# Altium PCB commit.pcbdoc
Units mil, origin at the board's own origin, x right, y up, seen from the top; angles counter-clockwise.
Board outline 1653.54 x 3149.61 mil, 2 copper layers (Top Layer, Bottom Layer); 82 components, 52 nets, 246 pads, 237 vias.
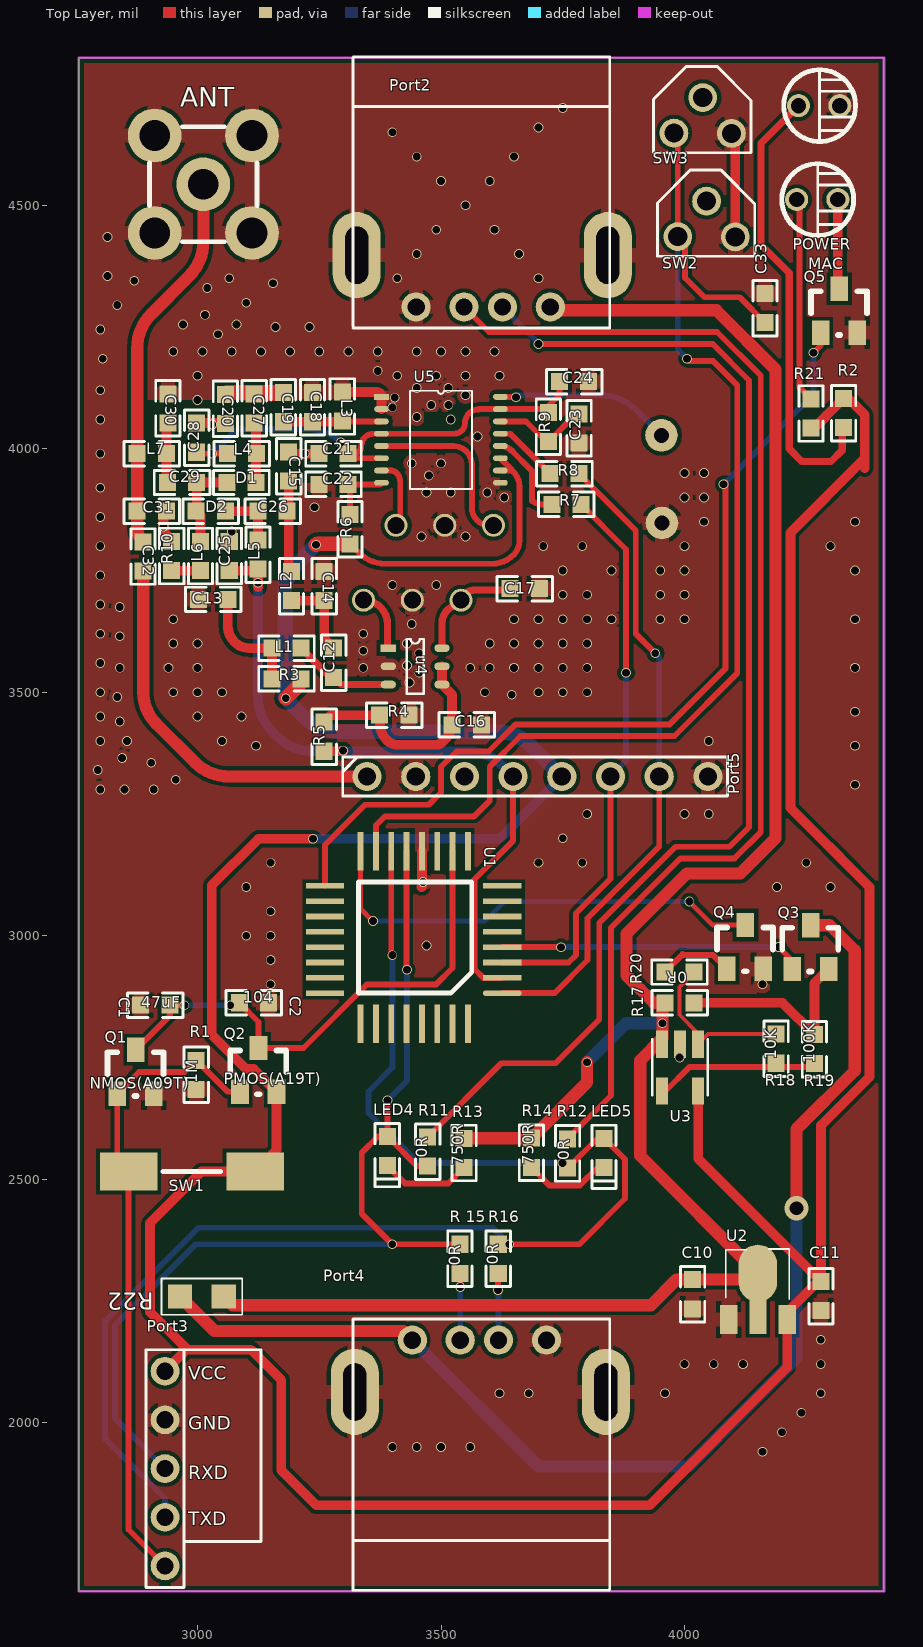
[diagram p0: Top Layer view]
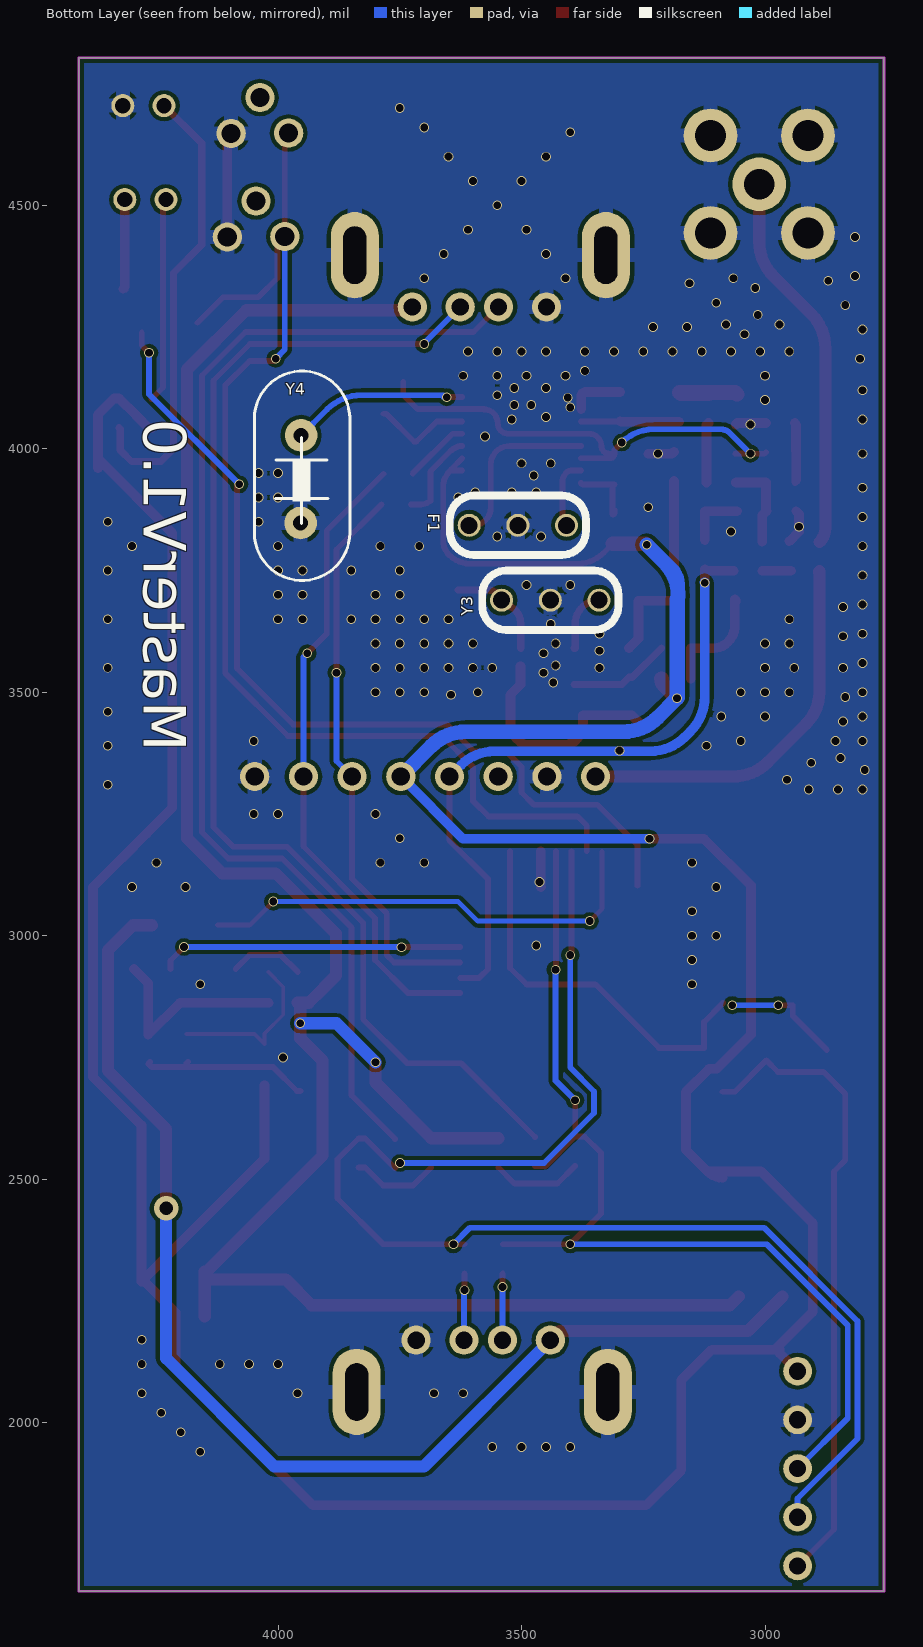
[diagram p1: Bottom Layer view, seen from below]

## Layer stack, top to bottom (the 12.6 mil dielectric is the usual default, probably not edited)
Top Layer: signal copper 1.4
Dielectric: dielectric 12.6, FR-4, Dk 4.8
Bottom Layer: signal copper 1.4

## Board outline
2755.91,1653.54 4409.45,1653.54 4409.45,4803.15 2755.91,4803.15

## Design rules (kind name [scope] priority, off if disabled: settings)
Clearance [All] p1: gap=8
ComponentClearance [All] p1: gap=0 collisioncheckmode=3 verticalgap=0 showdistances=FALSE
MinimumSolderMaskSliver [All] p1: minsoldermaskwidth=0
PolygonConnect [All] p1: connectstyle=Relief reliefconductorwidth=30 reliefentries=4 polygonreliefangle="90 Angle"
RoutingVias [All] p1: holewidth=50 width=100 viastyle="Through Hole" minholewidth=1 minwidth=10 maxholewidth=28 maxwidth=50
SilkToSilkClearance [All] p1: silktosilkclearance=0
SilkscreenOverComponentPads [All] p1: minsilkscreentomaskgap=0
SolderMaskExpansion [All] p1: expansion=4
Width [All] p1: maxlimit=30 minlimit=7 preferedwidth=15
24 further rules are at their usual default settings.

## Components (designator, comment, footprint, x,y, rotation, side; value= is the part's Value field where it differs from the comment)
ANT "SMA" SWA-KE天线母座 3011.81,4543.31 r0 top
C1 "47uF" 0603 2883,2857.17 r0 top
C2 "104" 0603 3145.67,2862.2 r180 top
C10 "10uF" 0603 4016.61,2293.64 r270 top
C11 "104" 0603 4280.39,2289.7 r270 top
C12 "220pF5%" 0603 3279.53,3590.55 r270 top
C13 "104" 0603 3001.97,3690.63 r0 top
C14 "4.7pF5%" 0603 3259.84,3748.03 r270 top
C15 "12pF5%" 0603 3187.01,3993.78 r270 top
C16 "104" 0603 3582.68,3433.07 r180 top
C17 "1pF" 0603 3641.73,3712.6 r0 top
C18 "NC" 0603 3235.98,4115.51 r270 top
C19 "1pF5%" 0603 3175.98,4115.51 r270 top
C20 "NC" 0603 3057.08,4111.89 r270 top
C21 "104" 0603 3309.05,3989.84 r180 top
C22 "104" 0603 3309.05,3926.85 r180 top
C23 "104" 0603 3783.46,4011.81 r90 top
C24 "104" 0603 3803.15,4137.8 r180 top
C25 "NC" 0603 3064.96,3749.69 r90 top
C26 "NC" 0603 3124.01,3871.73 r0 top
C27 "NC" 0603 3116.14,4052.84 r90 top
C28 "1045%" 0603 2998.03,4052.84 r270 top
C29 "220pF5%" 0603 2998.03,3930.79 r180 top
C30 "NC" 0603 2938.97,4052.84 r90 top
C31 "NC" 0603 2875.98,3871.73 r0 top
C32 "NC" 0603 2887.79,3808.74 r270 top
C33 "NC" 0603 4165.35,4318.9 r270 top
D1 "SMP1320" 0603 3120.08,3930.79 r180 top
D2 "SMP1320" 0603 3057.08,3871.73 r180 top
F1 "10.7M" "PT4450 XTAL" 3507.6,3842.8 r0 bottom
L1 "180nH5%" 0603 3212.6,3590.55 r180 top
L2 "22nH5%" 0603 3192.91,3748.03 r270 top
L3 "47nH5%" 0603 3297.24,4056.77 r90 top
L4 "180nH5%" 0603 3061.02,3989.84 r0 top
L5 "180nH5%" 0603 3124.01,3812.68 r270 top
L6 "180nH5%" 0603 3005.9,3749.69 r90 top
L7 "0R" 0603 2875.98,3989.84 r0 top
LED4 "RX" LED-0603 3389.76,2527.56 r90 top
LED5 "TX" LED-0603 3834.65,2523.62 r90 top
MAC "MAC" 2.54LED 4322.83,4511.81 r0 top
Port2 "USB_A" USB-A 3586.61,4291.34 r180 top
Port3 "DEBUG" STC_DEBUG 2933.07,1905.51 r0 top
Port4 "USB_B" USB-A 3578.74,2169.29 r0 top
Port5 "Mold" Pin-8 3748.03,3326.77 r90 top
POWER "POWER" 2.54LED 4326.77,4704.72 r0 top
Q1 "NMOS(A09T)" SOT-23 2870.08,2720.47 r0 top
Q2 "PMOS(A19T)" SOT-23 3122.05,2724.41 r0 top
Q3 "AO3407(P)" SOT-23 4255.91,2976.38 r0 top
Q4 "9014" SOT-23 4122.05,2976.76 r0 top
Q5 "NMOS(A09T)" SOT-23 4314.96,4283.46 r0 top
R1 "1M" 0603 2997.17,2683.94 r90 top
R2 "2.2K" 0603 4326.77,4043.31 r90 top
R3 "0R" 0603 3212.6,3527.56 r180 top
R4 "100k" 0603 3374.02,3452.76 r0 top
R5 "0R" 0603 3259.84,3378.77 r90 top
R6 "10R" 0603 3312.99,3804.8 r90 top
R7 "10K" 0603 3787.4,3885.83 r180 top
R8 "10K" 0603 3783.46,3948.82 r180 top
R9 "5.1M" 0603 3720.47,4074.8 r270 top
R10 "3.3K" 0603 2946.85,3749.69 r90 top
R11 "0R" 0603 3472.44,2586.61 r270 top
R12 "0R" 0603 3759.84,2582.68 r270 top
R13 "750R" 0603 3547.24,2523.62 r90 top
R14 "750R" 0603 3685.6,2524.06 r90 top
R16 "0R" 0603 3617.46,2306.19 r90 top
R17 "RES" 0603 4019.94,2862.13 r180 top
R18 "10K" 0603 4188.14,2737.91 r90 top
R19 "100K" 0603 4266.88,2796.97 r270 top
R20 "0R" 0603 4019.68,2925.2 r180 top
R21 "0R" 0603 4259.84,4102.36 r270 top
R22 "0R" 0805 3003.94,2263.78 r180 top
"R 15" "0R" 0603 3538.72,2306.19 r90 top
SW1 "REST" SW-1 3047.24,2437.01 r270 top
SW2 "REST" Key1 4102.36,4433.07 r180 top
SW3 "REST" Key1 4094.49,4645.67 r180 top
U1 "STC8F2K32S2" LQPF-32 3590.55,2846.46 r180 top
U2 "HT7533-1" 3A5A3D 4150.78,2211.88 r0 top
U3 "LM321" AD8628 3988.19,2732.28 r180 top
u4 "PT4450" PT4450 3389.76,3586.61 r270 top
U5 "PT4302" PT4302 3377.68,4106.58 r0 top
Y3 "433.92M" "PT4450 XTAL" 3440.94,3688.98 r180 bottom
Y4 "13.226M" "PT4306 XTAL" 3952.76,4027.56 r270 bottom

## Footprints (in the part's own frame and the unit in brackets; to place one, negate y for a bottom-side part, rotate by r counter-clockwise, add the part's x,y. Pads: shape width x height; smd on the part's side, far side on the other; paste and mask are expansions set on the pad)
2.54LED [mm]
  round 1.2 hole 0.8: 1(-2.35,0) 2(-0.2,0)
  silkscreen extent -3.12,-1.87 0.62,1.9
3A5A3D [mm]
  rect 0.9x1.5 smd: 1(-1.524,0) 3(1.524,0)
  rect 0.9x1.8 smd: 2(0,0.15)
  oval 2x3 smd: 2(0,2.4)
  silkscreen extent -1.68,1.07 1.63,3.67
0603 [mil]
  rect 35x35 smd: 1(0,0) 2(60,0)
  silkscreen extent -27,-25 87,25
0805 [mil]
  rect 50x50 smd: 1(-50,5) 2(40,5)
  silkscreen extent -88,-32 78,42
AD8628 [mil]
  rect 24x56 smd: 1(-39.61,-44.88) 2(-2.61,-44.88) 3(34.39,-44.88) 4(34.39,51.12) 5(-39.61,51.12)
  silkscreen extent -60,-55 54,60
Key1 [mm]
  round 1.5 / inner round 1.524 / far side round 1.524 hole 1: 1(2.95,-0.067) 2(-0.05,-0.05) ""(1.45,-1.92)
  silkscreen extent -1.07,-3.55 4.01,0.95
LED-0603 [mil]
  rect 35x35 smd: 1(0,0) 2(60,0)
  silkscreen extent -43,-25 87,25
LQPF-32 [mm]
  oct 2x0.3 smd: 1(-0.9,-0.9)
  rect 2x0.3 smd: 2(-0.9,-1.7) 3(-0.9,-2.5) 4(-0.9,-3.3) 5(-0.9,-4.1) 6(-0.9,-4.9) 7(-0.9,-5.7) 8(-0.9,-6.5) 17(8.35,-6.5) 18(8.35,-5.7) 19(8.35,-4.9) 20(8.35,-4.1) 21(8.35,-3.3) 22(8.35,-2.5) 23(8.35,-1.7) 24(8.35,-0.9)
  rect 0.3x2 smd: 9(0.9,-8.3) 10(1.7,-8.3) 11(2.5,-8.3) 12(3.3,-8.3) 13(4.1,-8.3) 14(4.9,-8.3) 15(5.7,-8.3) 16(6.5,-8.3) 25(6.5,0.7) 26(5.7,0.7) 27(4.9,0.7) 28(4.1,0.7) 29(3.3,0.7) 30(2.5,0.7) 31(1.7,0.7) 32(0.9,0.7)
  silkscreen extent 0.7,-6.7 6.6,-0.9
Pin-8 [mil]
  round 60 hole 37.4: 1(0,400) 2(0,300) 3(0,200) 4(0,100) 5(0,0) 6(0,-100) 7(0,-200) 8(0,-300)
  silkscreen extent -40,-340 40,450
PT4302 [mil]
  rect 30x12 smd: 1(0,0)
  oval 30x12 smd: 2(0,-25.2) 3(0,-50.39) 4(0,-75.59) 5(0,-100.79) 6(0,-125.98) 7(0,-151.18) 8(0,-176.38) 9(244.09,-176.38) 10(244.09,-151.18) 11(244.09,-125.98) 12(244.09,-100.79) 13(244.09,-75.59) 14(244.09,-50.39) 15(244.09,-25.2) 16(244.09,0)
  silkscreen extent 58,-189 186,13
"PT4306 XTAL" [mil]
  round 66.93 hole 31: 1(0,0) 2(180,-1)
  silkscreen extent -132,-96 298,100
PT4450 [mm]
  rect 0.4x0.8 smd: 1(-0.1,0.05)
  oval 0.4x0.8 smd: 2(0.85,0.05) 3(1.8,0.05) 4(1.8,2.85) 5(0.85,2.85) 6(-0.1,2.85)
  silkscreen extent -0.57,1 2.28,1.89
"PT4450 XTAL" [mm]
  round 1.2 hole 0.889: 1(-2.54,0) 2(0,0) 3(2.54,0)
  silkscreen extent -3.56,-1.55 3.56,1.55
SOT-23 [mil]
  rect 36x50 smd: 1(40,-45) 2(-35,-45) 3(3,45)
  silkscreen extent -55,-50 60,40
STC_DEBUG [mm]
  round 1.5 hole 0.9: 1(0,5.08) 2(0,2.54) 3(0,0) 4(0,-2.54) 5(0,-5.08)
  silkscreen extent -1,-6.2 5,6.2
SW-1 [mm]
  rect 2x3 smd: 1(-2,1.8) 2(-2,-4.8)
  silkscreen extent -2,-3 -2,0
SWA-KE天线母座 [mm]
  round 2.8 hole 1.6: 1(0,0) 2(-2.54,-2.54) 2(-2.54,2.54) 2(2.54,-2.54) 2(2.54,2.54)
  silkscreen extent -2.8,-3 2.8,3
USB-A [mm]
  round 1.524 hole 0.9: 1(-3.5,0) 2(-1,0) 3(1,0) 4(3.5,0)
  oval 2.5x4.5 hole 1.2 slot 3 at 90 deg: 4(-6.5,-2.7) 4(6.6,-2.7)
  silkscreen extent -6.6,-13.05 6.8,1.1

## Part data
ANT L1 L2 L3 R1 R2 R3 R4 R5 R6 R7 R8 R9 R10 R11 R12 R13 R14 R16 R17 R18 R19 R20 R21 R22 "R 15": library part Res2, "Resistor"
C1 C2 C10 C11 C12 C13 C14 C15 C16 C17 C18 C19 C20 C21 C22 C23 C24 C25 C26 C27 C28 C29 C30 C31 C32 C33: library part Cap, "Capacitor"
D1 D2 LED4 LED5 MAC POWER: library part DIODE, "diode"
F1: library part Filter
L4 L5 L6 L7: library part L, "Inductor"
Port2 Port4: library part USB
Port3: library part PIN-5
Port5: library part Pin-8
Q1 Q5: library part MOSFET-N, "mosfet"
Q2 Q3: library part MOSFET-P, "mosfet"
Q4: library part 2N3904, "NPN General Purpose Amplifier"
SW1 SW2 SW3: library part SW-P, "key"
U1: library part STC8F2K64S2
U3: library part AD8628
Y3: library part PT4450-XTAL
Y4: library part XTAL, "Crystal Oscillator"

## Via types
v1: diameter 20, hole 16, Top Layer to Bottom Layer, 236 vias
v2: diameter 50, hole 28, Top Layer to Bottom Layer, 1 vias

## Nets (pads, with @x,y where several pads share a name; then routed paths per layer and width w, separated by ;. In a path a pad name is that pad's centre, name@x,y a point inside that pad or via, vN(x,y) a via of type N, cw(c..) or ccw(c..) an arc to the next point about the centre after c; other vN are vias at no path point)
ANT: ANT.1 C31.1 C32.1 L7.1 | length 785.4
  Top Layer w25: C32.1 cw(c2916.31,3837.26) 2875.98,3837.26 C31.1 L7.1 2875.98,4206.32 cw(c2975.98,4206.32) 2905.27,4277.03 2982.52,4354.28 ccw(c2911.81,4424.99) 3011.81,4424.99 ANT.1
CEOUT: Q3.2 U1.4 | length 669.8
  Top Layer w12: U1.4 v1(3746.38,2976.38) ; v1(4193.24,2976.76) 4220.91,2949.09 Q3.2
  Bottom Layer w12: v1(3746.38,2976.38) 3824.62,2976.38 ; 4160,2976.76 4140,2976.76 ; v1(4193.24,2976.76) 4140,2976.76 ; 3824.62,2976.38 3825,2976.76 3850,2976.76 ; 3824.62,2976.38 3849.62,2976.38 3850,2976.76 ; 3850,2976.76 4140,2976.76
CNET: Q4.3 U1.16 | length 955.3
  Top Layer w10: U1.16 3334.65,3055.35 v1(3360,3030) ; v1(4010,3070) 4058.24,3021.76 Q4.3
  Bottom Layer w10: v1(3360,3030) 3590,3030 3630,3070 v1(4010,3070)
GND: ANT.2 C1.1 C2.1 C10.2 C11.2 C13.1 C14.1 C15.1 C16.1 C17.2 C18.1 C20.2 C21.2 C22.2 C23.1 C24.1 C25.2 C28.1 C30.2 C31.2 C33.1 F1.2 L3.2 Port2.4 Port3.2 Port4.4 Port5.2 Port5.8 POWER.2 Q1.1 Q4.1 Q5.1 R1.1 R4.2 R10.2 SW2.2 SW3.2 U1.12 U2.1 U3.2 u4.2 U5.1 U5.2 U5.9 Y3.2 Y4.2 | length 591.1
  Top Layer w20: C31.2 2930,3865.75 v1(2930,3840) 2930,3830 R10.2@2950,3810 ; C28.1 3057.16,4052.84 C20.2@3060,4050 ; C15.1 3190.79,3990 C21.2@3240,3990 ; L3.2 3367.48,4116.77 cw(c3367.48,4106.58) U5.1 U5.2 ; 3460,3100 ccw(c3460,3100.63) 3460.63,3100.63 U1.12 ; SW3.2 4104.33,4639.76 SW2.2
  other v1: 4160,1940 3400,1950 3450,1950 3500,1950 3560,1950 4200,1980 4240,2020 3620,2060 3680,2060 3960,2060 4280,2060 4000,2120 4060,2120 4120,2120 4280,2120 4280,2170 3990,2750 3150,2900 4160,2900 3150,2950 3470,2980 3100,3000 3150,3000 3150,3050 3100,3100 4190,3100 4300,3100 3463,3110.24 3150,3150 3700,3150 3790,3150 4250,3150 3750,3200 3800,3250 4000,3250 4050,3250 2800,3300 2850,3300 2910,3300 4350,3310 2955,3320 2795,3340 2905,3355 2845,3365 3120,3390 4350,3390 2800,3400 2855,3400 3050,3400 4050,3400 2840,3440 2800,3450 3000,3450 3090,3450 4350,3460 2835,3490 3645,3495 2800,3500 2950,3500 3000,3500 3050,3500 3590,3500 3700,3500 3750,3500 3800,3500 3435,3520 3455,3540 2840,3550 2940,3550 3000,3550 3340,3550 3560,3550 3600,3550 3650,3550 3700,3550 3750,3550 3800,3550 4350,3550 3430,3555 2800,3560 3455,3580 3340,3585 2950,3600 3000,3600 3430,3600 3600,3600 3650,3600 3700,3600 3750,3600 3800,3600 2840,3615 2800,3620 3340,3620 3440,3640 2950,3650 3650,3650 3700,3650 3750,3650 3800,3650 3850,3650 3950,3650 4000,3650 4350,3650 2840,3675 2800,3680 3750,3700 3800,3700 3950,3700 4000,3700 3400,3720 3490,3720 2800,3740 3750,3750 3850,3750 3950,3750 4000,3750 4350,3750 2800,3800 3710,3800 3790,3800 4000,3800 4300,3800 3460,3820 3550,3820 3070,3830 4040,3850 4350,3850 2800,3860 3240,3880 3630,3900 4000,3900 4040,3900 3470,3910 3520,3910 3595,3910 2800,3920 3475,3945 4000,3950 4040,3950 3440,3970 3500,3970 2800,3990 3220,3990 3575,4025 3030,4050 2800,4060 3520,4060 3450,4065 3400,4085 3480,4090 3515,4090 3000,4100 3405,4105 3550,4110 2800,4120 3450,4125 3515,4125 3000,4150 3410,4150 3490,4150 3550,4150 3620,4150 3370,4160 2805,4185 2950,4200 3010,4200 3070,4200 3130,4200 3190,4200 3250,4200 3310,4200 3370,4200 3450,4200 3500,4200 3550,4200 3610,4200 3042,4235 2800,4245 3160,4250 3230,4250 2970,4255 3080,4255 3015,4275 2835,4295 3100,4300 3020,4330 3155,4340 2870,4345 3065,4350 3410,4350 3700,4350 2815,4355 3450,4400 3660,4400 2815,4435 3490,4450 3610,4450 3550,4500 3500,4550 3600,4550 3450,4600 3650,4600 3400,4650 3700,4660 3750,4700
NetC12_1: C12.1 C14.2 L2.2 | length 172.6
  Top Layer w20: L2.2 C14.2 3259.84,3610.24 C12.1
NetC12_2: C12.2 L1.1 u4.3 | length 210.1
  Top Layer w15: L1.1 3272.6,3530.55 C12.2 3294.33,3515.75 u4.3
NetC13_2: C13.2 L1.2 R3.2 | length 239.8
  Top Layer w20: C13.2@3059.91,3685.67 cw(c3066.92,3685.67) C13.2 3061.97,3637.21 ccw(c3110.77,3637.21) 3076.26,3602.7 ccw(c3105.6,3632.05) 3105.6,3590.55 L1.2 R3.2
NetC16_2: C16.2 R4.1 R5.2 u4.4 u4.5 | length 464
  Top Layer w20: R5.2 3273.83,3452.76 R4.1 3374.02,3437.65 ccw(c3425.83,3437.65) 3389.19,3401.01 ccw(c3411.24,3423.06) 3411.24,3391.88 3489.67,3391.88 ccw(c3489.67,3408.57) 3501.46,3396.77 3512.01,3407.31 ccw(c3486.25,3433.07) C16.2 3522.68,3495.04 u4.4 u4.5
NetC17_1: C17.1 u4.6 Y3.1 | length 227
  Top Layer w15: u4.6 3501.97,3641.97 cw(c3540,3641.97) 3540,3680 cw(c3570,3680) 3570,3710 C17.1@3630,3710
  Top Layer w30: Y3.1 Y3.1@3547.09,3695.12
NetC18_2: C18.2 C19.2 L3.1 U5.3 | length 203.9
  Top Layer w12: L3.1@3295.98,4055.51 cw(c3296.65,4055.51) 3296.65,4056.18 U5.3
  Top Layer w20: C19.2 C18.2 3295.98,4055.51 L3.1
NetC22_1: C22.1 R6.2 U5.8 | length 219.5
  Top Layer w12: U5.8 cw(c3374.33,3930.2) 3374.33,3926.85 C22.1 ; R6.2@3309.05,3868.74 ccw(c3312.99,3868.74) R6.2 ; R6.2@3309.05,3868.74 ccw(c3312.99,3868.74) R6.2 ; R6.2@3309.05,3868.74 ccw(c3312.99,3868.74) R6.2 ; R6.2@3309.05,3868.74 ccw(c3312.99,3868.74) R6.2 ; C22.1 cw(c3309.05,3922.92) C22.1@3312.99,3922.92 ; C22.1 cw(c3309.05,3922.92) C22.1@3312.99,3922.92 ; C22.1 cw(c3309.05,3922.92) C22.1@3312.99,3922.92 ; C22.1 cw(c3309.05,3922.92) C22.1@3312.99,3922.92 ; C22.1 cw(c3309.05,3922.92) C22.1@3312.99,3922.92 ; C22.1 cw(c3309.05,3922.92) C22.1@3312.99,3922.92 ; C22.1 3312.99,3926.85 R6.2 ; R6.2 cw(c3322.49,3874.31) 3309.05,3874.31 ccw(c3322.49,3874.31) R6.2
NetC23_2: C23.2 R9.2 U5.14 | length 202.4
  Top Layer w12: U5.14 3674.27,4056.18 3715.64,4014.8 3720.93,4014.8 3777.94,4071.81 C23.2
NetC26_1: C26.1 D2.1 L5.1 | length 126
  Top Layer w20: D2.1 C26.1 L5.1
NetC27_1: C27.1 D1.1 L4.2 | length 123.7
  Top Layer w20: C27.1 3120.08,4048.9 D1.1
NetC29_1: C29.1 D1.2 D2.2 L6.2 | length 197.3
  Top Layer w15: C29.1@2997.08,3928.51 cw(c3000.31,3928.51) C29.1 ccw(c3000.31,3928.51) C29.1@2997.08,3928.51
  Top Layer w20: L6.2 3005.9,3862.92 D2.2 ; D1.2 C29.1 2998.03,3872.68 D2.2 ; D2.2 ccw(c2994.8,3874.02) 2998.03,3874.02 cw(c2994.8,3874.02) D2.2
NetC29_2: C29.2 C30.1 L7.2 | length 195.2
  Top Layer w15: C29.2@2935.98,3935.73 ccw(c2942.97,3935.73) C29.2 ; L7.2 ccw(c2928.76,3997.07) 2938.97,3997.07 C30.1
  Top Layer w20: C29.2@2935.98,3935.73 L7.2 C30.1@2935.98,4045.61 ; C30.1@2935.98,4045.61 cw(c2946.2,4045.61) C30.1 ccw(c2946.2,4045.61) C30.1@2935.98,4045.61
NetC32_2: C32.2 Port5.1 | length 798.2
  Top Layer w25: C32.2@2889.26,3745.19 ccw(c2884.24,3745.19) C32.2 cw(c2886.33,3747.28) 2888.4,3747.28 2888.4,3500.03 ccw(c2979.98,3500.03) 2915.22,3435.27 2994.43,3356.06 ccw(c3065.15,3426.77) 3065.15,3326.77 Port5.1
NetC33_2: C33.2 SW2.1 SW3.1 U1.15 | length 2448.6
  Top Layer w12: U1.15 3366.14,3226.14 3385,3245 3568,3245 3600.03,3277.03 3600.03,3346.65 3663.38,3410 3979.5,3410 4108.5,3539 4108.5,4130.48 4058.98,4180 4010,4180 v1(4005,4185) ; SW3.1@3986.22,4640.44 SW2.1 4001.28,4435.72 4001.28,4350.72 4040.94,4311.06 4113.2,4311.06 C33.2
  Bottom Layer w12: SW2.1 3986.22,4203.78 v1(4005,4185)
NetF1_1: F1.1 U5.7 | length 144.1
  Top Layer w12: U5.7 3396.22,3955.39 cw(c3396.22,3937.94) 3408.56,3950.28 cw(c3390.05,3931.77) 3416.23,3931.77 3416.23,3873.99 3416.23,3863.65 cw(c3386.75,3863.65) F1.1
NetF1_3: F1.3 U5.5 | length 361.1
  Top Layer w12: U5.5 3524.89,4005.79 cw(c3524.89,3967.38) 3563.31,3967.38 ccw(c3563.31,3967.29) 3563.22,3967.29 3563.22,3878.89 ccw(c3599.32,3878.89) 3599.32,3842.8 F1.3
NetL6_1: L6.1 R10.1 | length 59.1
  Top Layer w20: R10.1 L6.1
NetLED4_1: LED4.1 R13.1 | length 186
  Top Layer w12: LED4.1 3426.21,2491.11 3514.74,2491.11 R13.1
NetLED5_1: LED5.1 R14.1 | length 179.4
  Top Layer w12: R14.1 3722.49,2487.18 3784.8,2487.18 3821.24,2523.62 LED5.1
NetMAC_1: MAC.1 R21.1 | length 421.7
  Top Layer w12: MAC.1 4236.5,4505.63 4236.5,4125.7 R21.1
NetMAC_2: MAC.2 Q5.3 | length 197
  Top Layer w20: MAC.2@4306.15,4503 MAC.2 4314.96,4331.46 Q5.3
NetPort2_2: Port2.2 R11.1 | length 2527.7
  Top Layer w12: R11.1 3623.83,2738 3735,2738 3825,2828 3825,3025.94 3981.56,3182.5 4092.43,3182.5 4132.5,3222.57 4132.5,4140.43 4057.93,4215 v1(3700,4215)
  Bottom Layer w12: Port2.2 3700,4217.32 v1(3700,4215)
NetPort2_3: Port2.3 R12.1 | length 2464.6
  Top Layer w12: Port2.3 3598.58,4240 4066.87,4240 4156.5,4150.37 4156.5,3212.63 4102.37,3158.5 3991.5,3158.5 3849,3016 3849,2671.83 R12.1
NetPort4_2: "R 15.1" Port4.2 | length 137.2
  Top Layer w12: 3538.72,2306.19 3539.37,2305.54 v1(3539.37,2278.56)
  Bottom Layer w12: Port4.2 v1(3539.37,2278.56)
NetPort4_3: Port4.3 R16.1 | length 137.6
  Top Layer w12: v1(3617,2272) 3617,2305.72 R16.1
  Bottom Layer w12: v1(3617,2272) 3618.11,2270.89 Port4.3
NetPOWER_1: POWER.1 R2.1 | length 937.5
  Top Layer w15: POWER.1 4157,4627.47 4157,4419 4215,4361 4215,4000 4241,3974 4301,3974 4324,3997 4324,4040.54 R2.1
NetQ3_1: Q3.1 R17.1 R19.1 | length 420.4
  Top Layer w20: R17.1 4201.72,2862.13 R19.1 4266.88,2902.35 Q3.1
NetQ4_2: Q4.2 R20.2 | length 205.3
  Top Layer w12: 3996.03,2962 3959.68,2925.65 R20.2 3994.49,2960 4058.8,2960 Q4.2
NetQ5_2: Q5.2 U1.17 | length 1871.2
  Top Layer w12: U1.17 3261.81,3186.81 3344,3269 3475,3269 3500.03,3294.03 3500.03,3346.65 3531.55,3378.17 3597.6,3378.17 3653.44,3434 3969.56,3434 4084.5,3548.94 4084.5,3931.5 v1(4080,3927) ; v1(4265,4197) 4268.15,4200.15 4279.96,4211.96 Q5.2
  Bottom Layer w12: v1(4080,3927) 4265,4112 v1(4265,4197)
NetR7_2: R7.2 U5.12 | length 217.2
  Top Layer w12: 3646.42,3995.58 ccw(c3621.77,3970.92) U5.12 cw(c3621.77,3975.75) 3643.01,3996.99 cw(c3643.01,3994.58) 3644.72,3996.28 3686,3955 cw(c3683.59,3952.59) 3687,3952.59 3687,3893 3688,3893 ccw(c3705.32,3910.32) 3705.32,3885.83 R7.2 R7.2@3726,3885.83
NetR8_2: R8.2 U5.13 | length 136.1
  Top Layer w12: U5.13 3642.01,4030.99 3723.46,3949.54 R8.2
NetR18_1: R18.1 R19.2 U3.4 | length 346.3
  Top Layer w12: U3.4 3961.17,2681.17 4010,2730 4259.91,2730 R19.2 R19.2@4262.84,2741 ; R18.1@4185.05,2741 R18.1
NetR18_2: R18.2 R20.1 U3.1 | length 345.4
  Top Layer w8: R20.1 3989.44,2894.95 3989.44,2837.56 4027.8,2799.2 U3.1 4048.54,2797.91 R18.2
Netu4_1: u4.1 Y3.3 | length 390.7
  Top Layer w15: u4.1@3390,3590 u4.1@3390,3592.28 ; Y3.3 cw(c3340.94,3639.92) 3390,3639.92 ; Y3.3 cw(c3340.94,3639.92) 3390,3639.92 ; Y3.3 cw(c3340.94,3639.92) 3390,3639.92 ; Y3.3 cw(c3340.94,3639.92) 3390,3639.92 ; u4.1@3390,3592.28 ccw(c3391.73,3592.28) u4.1 ; u4.1@3390,3592.28 ccw(c3391.73,3592.28) u4.1 ; u4.1@3390,3592.28 ccw(c3391.73,3592.28) u4.1 ; u4.1@3390,3592.28 ccw(c3391.73,3592.28) u4.1 ; u4.1@3390,3592.28 ccw(c3391.73,3592.28) u4.1 ; u4.1@3390,3592.28 ccw(c3391.73,3592.28) u4.1 ; u4.1@3390,3592.28 ccw(c3391.73,3592.28) u4.1 ; u4.1@3390,3592.28 ccw(c3391.73,3592.28) u4.1 ; u4.1@3390,3592.28 ccw(c3391.73,3592.28) u4.1 ; u4.1@3390,3592.28 ccw(c3391.73,3592.28) u4.1 ; u4.1@3390,3592.28 3390,3639.92
  Top Layer w30: Y3.3 Y3.3@3344.73,3685.19
NetU5_16: U5.16 Y4.1 | length 365.8
  Top Layer w12: U5.16 v1@3653.89,4106.58 ; v1(3653.79,4106) cw(c3655.47,4106) v1@3653.89,4106.58 ; v1@3653.89,4106.58 cw(c3655.47,4106) 3655.47,4107.68 cw(c3654.37,4107.68) 3654.37,4106.58 v1@3653.89,4106.58
  Bottom Layer w12: v1(3653.79,4106) v1@3660,4106 ; v1@3660,4110 3828.89,4110 cw(c3828.89,4010) 3899.6,4080.71 Y4.1
RFRXD: Port5.7 R8.1 U1.1 | length 1331.1
  Top Layer w12: U1.1 3732.89,2881.89 3801,2950 3801,3035.88 3948.03,3182.91 Port5.7 ; R8.1 3900,3832.28 3900,3620 v1(3940,3580)
  Bottom Layer w12: v1(3940,3580) 3948.03,3571.97 Port5.7
RFTXD: C25.1 L5.2 Port5.4 R5.1 U1.2 | length 1447.5
  Top Layer w12: U1.2 3586.75,2913.39 3568.61,2931.52 3568.61,3115.72 3648.03,3195.14 Port5.4
  Top Layer w20: C25.1 3096.22,3749.69 3121.02,3749.69 L5.2 3124.01,3715.98 cw(c3123.39,3715.98) 3123.83,3715.54 v1(3123.83,3724.95) ; R5.1 3300,3378.77 v1(3298.77,3380)
  Bottom Layer w20: v1@3124.13,3725.68 ccw(c3124.87,3724.95) v1(3123.83,3724.95) 3123.83,3490.34 ccw(c3223.83,3490.34) 3153.12,3419.63 3164.47,3408.27 ccw(c3235.19,3478.98) 3235.19,3378.98 ccw(c3235.7,3379.5) 3235.7,3378.77 3260,3378.77 3555.62,3378.77 cw(c3555.62,3281.21) 3624.61,3350.2
RX: C19.1 C20.1 C27.2 | length 183.9
  Top Layer w30: C20.1@3059.37,4112.84 ccw(c3059.37,4109.61) C20.1 3060.71,4115.51 C19.1 3173.31,4112.84 C27.2
RXCE: Port5.6 R7.1 U1.3 | length 1169.1
  Top Layer w12: U1.3 3761.94,2944.88 3777,2959.94 3777,3045.82 3823.26,3092.08 3848.03,3116.85 Port5.6 Port5.6@3844.56,3323.3 ; R7.1 3880,3793.23 v1(3880,3540)
  Bottom Layer w12: Port5.6 3880,3358.74 3880,3440 v1(3880,3540)
RXD: "R 15.2" LED4.2 Port3.3 R11.2 U1.13 | length 2105.8
  Top Layer w12: v1(3390,2662) 3389.76,2661.76 LED4.2 ; U1.13 3429.13,2930.87 v1(3430,2930) ; R11.2 3451.16,2526.61 3390.22,2587.56 LED4.2 ; 3538.72,2366.19 v1(3399.81,2366.19) 3337,2429 3337,2554 3370.56,2587.56 LED4.2
  Bottom Layer w12: Port3.3 2830,2008.58 2830,2199.95 2996.23,2366.19 v1(3399.81,2366.19) ; v1(3390,2662) 3430,2702 v1(3430,2930)
TRG: Port3.5 Q1.2 Q2.2 R1.2 SW1.2 | length 1317.6
  Top Layer w12: Port3.5 2858.27,1780.32 SW1.2 2835.08,2538.94 Q1.2 2879.61,2720 2973.23,2720 R1.2 3061.7,2679.41 Q2.2
TX: C15.2 C26.2 L2.1 | length 188.2
  Top Layer w20: C15.2 3187.01,3753.94 L2.1
TXD: LED5.2 Port3.4 R12.2 R16.2 U1.14 | length 2932.7
  Top Layer w12: U1.14 3397.64,2962.36 v1(3400,2960) ; R16.2 3784.19,2366.19 3878,2460 3878,2540.72 3835.1,2583.62 LED5.2 3821.24,2583.62 3760.3,2522.68 R12.2 v1(3749.52,2533)
  Bottom Layer w12: Port3.4 2933.07,1843.95 2810,1967.03 2810,2208.24 3001.76,2400 3606.19,2400 v1(3640,2366.19) ; v1(3400,2960) 3400,2729 3351,2680 3351,2636 3454,2533 v1(3749.52,2533)
V2: C21.1 C24.2 C28.2 L4.1 R9.1 U5.4 U5.6 U5.15 | length 1355.6
  Top Layer w12: C28.2 3001.02,3989.84 L4.1 3060.87,3990 v1(3030,3990) ; v1(3294.05,4012.95) 3309.05,3997.95 C21.1 ; U5.6 3340.62,3980.59 3318.31,3980.59 cw(c3318.31,3989.84) C21.1 ; C24.2 3743.15,4110.63 3713.9,4081.38 U5.15 3577.93,4081.38 ccw(c3577.93,4080.98) 3577.53,4080.98 ccw(c3577.53,4052.45) 3549,4052.45 3549,4052.14 cw(c3527.84,4052.14) 3527.84,4030.99 U5.4 3361.6,4030.99 ccw(c3361.6,4005.44) 3336.05,4005.44 cw(c3320.46,4005.44) 3320.46,3989.84 C21.1
  Bottom Layer w12: v1@3034.02,3990 v1(3030,3990) 3072.93,4032.93 cw(c3090,4015.86) 3090,4040 3228.74,4040 ; 3110,4040 3228.74,4040 ; 3228.74,4040 cw(c3228.74,3947.63) v1(3294.05,4012.95) ; 3228.74,4040 cw(c3228.74,3947.63) v1(3294.05,4012.95) ; 3228.74,4040 cw(c3228.74,3947.63) v1(3294.05,4012.95) ; 3228.74,4040 cw(c3228.74,3947.63) v1(3294.05,4012.95)
VCC: C11.1 Port3.1 Port5.5 Q2.1 R2.2 R3.1 R6.1 R21.2 SW1.1 U2.3 U3.5 U5.10 U5.11 | length 8655.7
  Top Layer w12: R6.1 3331.73,3786.07 ccw(c3385,3839.34) 3385,3764 3605.54,3764 ccw(c3605.54,3825.46) 3649,3782 ccw(c3620.03,3810.97) 3661,3810.97 3661,3923.03 ccw(c3620.03,3923.03) 3649,3952 ccw(c3640.8,3943.8) 3640.8,3955.39 U5.10 U5.10@3627.01,3955.39 ; U5.11 3645,3957.36 3645,3955
  Top Layer w20: Port3.1 2970,2142.44 2970,2150 ; SW1.1@3087.33,2503 ccw(c3087.33,2546.52) SW1.1 ; v1(3237,3199) 3125,3199 3029,3103 3029,2797 3099.59,2726.41 3115.05,2726.41 Q2.1 3162.05,2559.69 SW1.1 ; U3.5@4028.05,2692.9 4028.05,2542.04 C11.1 ; R21.2@4260.2,4042 4265.46,4042 4291.27,4067.81 4291.27,4068.26 4326.32,4103.31 R2.2 4336.69,4103.31 4370,4070 4370,3980 ; 4320,3160 4270,3210 ; 4370,3960 4370,3980 ; SW1.1 3007.75,2515.75 2902,2410 2902,2227 2979.39,2149.61 3109.39,2149.61 3172,2087 3172,1902 3244,1830 3928,1830 4210.78,2112.78 U2.3 4210.78,2226.21 4274.27,2289.7 C11.1 ; 4270,3210 4380,3100 4380,2710 4280.39,2610.39 C11.1 ; 4270,3210 4217.5,3262.5 4217.5,3827.5 4370,3980
  Top Layer w30: v1@3180.82,3487.56 cw(c3180.95,3487.56) v1(3180.86,3487.65) 3206.82,3513.61 ccw(c3192.87,3527.56) R3.1 ; v1(3243.09,3803.03) cw(c3247.38,3798.74) 3247.38,3804.8 R6.1
  Bottom Layer w20: v1(3237,3199) 3620.26,3199 Port5.5
  Bottom Layer w30: v1@3182,3490.4 cw(c3178.11,3490.4) v1@3180.87,3487.66 ; Port5.5 3685.3,3389.5 ccw(c3614.59,3318.79) 3614.59,3418.79 3291.14,3418.79 cw(c3291.14,3518.79) 3220.43,3448.08 v1(3180.86,3487.65) ; 3179.05,3695.31 ccw(c3171.1,3689.62) 3178.01,3696.53 cw(c3278.01,3696.53) 3179.05,3710.88 ; 3179.05,3695.31 cw(c3171.1,3689.62) 3180.87,3689.62 v1@3180.87,3487.66 ; 3179.05,3695.31 3179.05,3492.03 ccw(c3185.24,3492.03) v1(3180.86,3487.65) ; 3179.05,3695.31 3179.05,3710.88 ; 3179.05,3710.88 cw(c3278.01,3696.53) 3207.3,3767.24 v1(3243.09,3803.03) 3191.93,3751.88 ccw(c3221.63,3722.18) 3179.64,3722.18 3179.64,3714.74 cw(c3177.62,3714.74) 3179.05,3713.32 3179.05,3710.88
VCC_5V: C10.1 Port2.1 R13.2 R14.2 R17.2 R22.1 U2.2 U3.3 | length 4480.1
  Top Layer w25: R22.1 3071.72,2241 3931,2241 3983.64,2293.64 4138.05,2293.64 4150.78,2306.37 3909,2548.15 3909,2743.85 3954.05,2788.9 3954.55,2789.4 R17.2@3954.55,2856.74 ; R13.2 3547.69,2584.06 R14.2 3800,2698.46 v1(3800,2740) ; Port2.1 3731.19,4284.56 4065.44,4284.56 4187,4163 4187,3200 4115,3128 4005,3128 3881,3004 3881,2918 3905.53,2893.47 ; 3909,2890 3936.87,2862.13 R17.2 R17.2@3954.55,2856.74 ; R17.2@3954.05,2856.24 R17.2@3954.55,2856.74 ; U2.2@4150.78,2217.79 U2.2@4150.78,2310.22
  Bottom Layer w25: v1(3800,2740) 3880,2820 v1(3954.55,2820)
VCORE: C1.2 C2.2 Q1.3 Q2.3 U1.10 | length 1064.1
  Top Layer w12: Q1.3 2943,2835.39 C1.2 v1(2972.83,2857.17) ; v1(3067.17,2857.17) C2.2@3070,2860 ; C2.2 3125.05,2822.83 Q2.3 3217.41,2769.41 3348,2900 3490,2900 3523.62,2933.62 3523.62,3100 U1.10
  Bottom Layer w12: v1(2972.83,2857.17) v1(3067.17,2857.17)
VOUT: Port4.1 Q3.3 R22.2 | length 2501.9
  Top Layer w25: R22.2 3034.72,2188 3422.24,2188 Port4.1 ; v2(4230,2440) 4230,2603.13 4349.5,2722.63 4349.5,2970 4298.12,3021.38 Q3.3
  Bottom Layer w25: Port4.1 3700.24,1910 3860,1910 4008,1910 4230,2132 v2(4230,2440)
pads on no net: Port5.3 SW2. SW3. U1.5 U1.6 U1.7 U1.8 U1.9 U1.11 U1.18 U1.19 U1.20 U1.21 U1.22 U1.23 U1.24 U1.25 U1.26 U1.27 U1.28 U1.29 U1.30 U1.31 U1.32

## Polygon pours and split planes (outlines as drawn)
GND on Top Layer "Top Layer-No Net" (solid, remove dead copper, pour order 1000): 2650,4980 2630,4960 2630,1540 5020,1540 5120,1440 4780,1780 4780,5060
GND on Bottom Layer "Top Layer-No Net" (solid, remove dead copper): 2590,5090 cw(c2565.86,5065.86) 2600,5065.86 2600,1580 5228.58,1580 cw(c5228.58,1480) 5299.29,1550.71 5350,1500 4609.29,2240.71 cw(c4680,2311.42) 4580,2311.42 4580,5040

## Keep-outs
Keep-Out Layer:
  the board outline again, w6

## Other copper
Top Layer:
  pour cut-out: 3340,4100 2880,4100 2880,3730 3180,3730 3170,3740 3170,3930 3340,3930

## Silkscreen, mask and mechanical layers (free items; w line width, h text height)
Bottom Overlay:
  text "MasterV1.0" at 4304.8,3377.85 h150 r90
